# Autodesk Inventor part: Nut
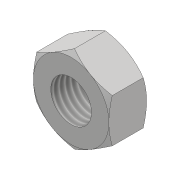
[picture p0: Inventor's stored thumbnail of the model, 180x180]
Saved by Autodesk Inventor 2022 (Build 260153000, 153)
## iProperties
Created: 2016-05
Part Number: Nut
Material: Generic
Document SubType Name: Modeling
Designer: CADCIM
Density: 1 g/cm^3
Appearance: Default
Author: CADCIM
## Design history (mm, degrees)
sketch "Sketch1"
  geometry: L1 (0, -18.475)-(-16, -9.238); L2 (-16, -9.238)-(-16, 9.238); L3 (-16, 9.238)-(0, 18.475); L4 (0, 18.475)-(16, 9.238); L5 (16, 9.238)-(16, -9.238); L6 (16, -9.238)-(0, -18.475); 2 further points
  constraints: 12 end point, 1 coincident, 13 other
  dimensions: "d0" = 32 distance between parallel lines of L2 L5
extrude "Extrusion1" new body sketch "Sketch1" distance "d1" = 16; taper "d2" = 0 deg
sketch "Sketch2"
  geometry: L1 (16, -9.238)-(16, 9.238) reference; C1 r 16 at (0, 0); 1 further point
  constraints: 1 centre point, 1 coincident, 1 tangent
extrude "Extrusion2" sketch "Sketch2" distance "d3" = 16; taper "d4" = 60 deg
sketch "Sketch3"
  geometry: L1 (0, -18.475)-(16, -9.238) reference; C1 r 16 at (0, 0); 1 further point
  constraints: 1 centre point, 1 coincident, 1 tangent
extrude "Extrusion3" sketch "Sketch3" distance "d5" = 16; taper "d6" = 60 deg
hole "Hole1" diameter "d9" = 17.294; stored, may be unused: countersink angle "d13" = 90 deg, drill point angle "d15" = 118 deg; dims "d7" = 10, "d8" = 10, "d10" = 40, "d11" = 4, "d12" = 2, "d14" = 51.2
body "Solid1"
